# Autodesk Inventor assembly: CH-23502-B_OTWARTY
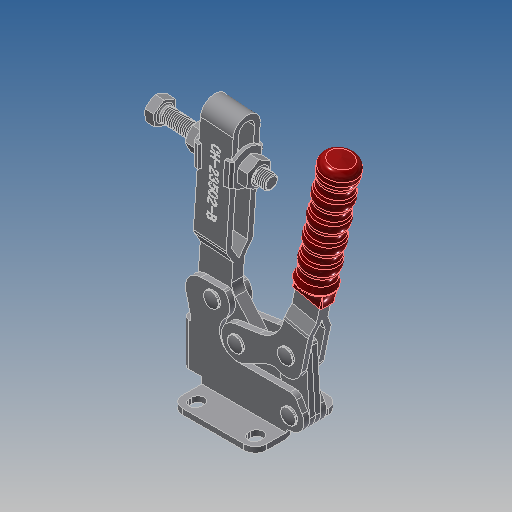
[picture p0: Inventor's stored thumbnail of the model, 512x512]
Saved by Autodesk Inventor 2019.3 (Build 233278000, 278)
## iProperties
Company: ·L?¤¤?
Created: 2010-06
Part Number: CH-23502-B_OTWARTY
Material: Ogólny
Description: STEP AP203
Document SubType Name: Assembly
Designer: CADENGINEERING4
Sending System: SolidWorks 2005179
Preprocessor: SwSTEP 2.0
Title: CH-23502-B.STEP
Author: ·L?¥Î?
Revision Number: ANY
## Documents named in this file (11)
- E:\STRONA\Horizontal toggle clamp\CH-23502-B\CH-23502-B_OTWARTY.iam
- E:\STRONA\Horizontal toggle clamp\CH-23502-B\CH-FC-107512___.ipt
- E:\STRONA\Horizontal toggle clamp\CH-23502-B\23502-B-05___.ipt
- E:\STRONA\Horizontal toggle clamp\CH-23502-B\23502-B-06___.ipt
- E:\STRONA\Horizontal toggle clamp\CH-23502-B\M10___.ipt
- E:\STRONA\Horizontal toggle clamp\CH-23502-B\23502-B-04___.ipt
- E:\STRONA\Horizontal toggle clamp\CH-23502-B\23502-B-07___.ipt
- E:\STRONA\Horizontal toggle clamp\CH-23502-B\23502-B-03___.ipt
- E:\STRONA\Horizontal toggle clamp\CH-23502-B\FW380___.ipt
- E:\STRONA\Horizontal toggle clamp\CH-23502-B\23502-B-02___.ipt
- E:\STRONA\Horizontal toggle clamp\CH-23502-B\23502-B-01___.ipt
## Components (19 placed, 19 different names)
1. CH-FC-107512_??_1 — Zestawiające:5, Zestawiające:7, Równoległe:1, Zestawiające:9, Zestawiające:11, Zestawiające:13
2. 23502-B-05_??_2 — Zestawiające:14, Zestawiające:15
3. 23502-B-06_??_3 — Zestawiające:38, Zestawiające:39
4. M10_??_4 — Zestawiające:11, Zestawiające:12
5. 23502-B-04_??_5 — Zestawiające:22, Zestawiające:23, Zestawiające:24, Zestawiające:25, Zestawiające:26, Zestawiające:34
6. 23502-B-05_??_6 — Zestawiające:16, Zestawiające:17, Zestawiające:18
7. M10_??_7 — Zestawiające:7, Zestawiające:8, Równoległe:1
8. 23502-B-07_??_8 — Zestawiające:1, Zestawiające:2, Zestawiające:3
9. 23502-B-05_??_9 — Zestawiające:29, Zestawiające:32, Zestawiające:34
10. 23502-B-04_??_10 — Zestawiające:22, Zestawiające:23, Zestawiające:24, Zestawiające:33
11. 23502-B-03_??_11 — Zestawiające:1, Zestawiające:2, Zestawiające:3, Zestawiające:29, Zestawiające:30, Zestawiające:31, Zestawiające:32, Zestawiające:33, Zestawiające:35, Zestawiające:36, Zestawiające:38, Zestawiające:39, Przejściowe:1
12. 23502-B-06_??_12 — Zestawiające:27, Zestawiające:28
13. FW380_??_13 — Zestawiające:9, Zestawiające:10, Zestawiające:12
14. FW380_??_14 — Zestawiające:4, Zestawiające:5, Zestawiające:6, Zestawiające:8
15. 23502-B-06_??_15 — Zestawiające:20, Zestawiające:21
16. 23502-B-02_??_16 — Zestawiające:4, Zestawiające:6, Zestawiające:10, Zestawiające:13, Zestawiające:18, Zestawiające:19, Zestawiające:37
17. 23502-B-06_??_17 — Zestawiające:35, Zestawiające:36
18. 23502-B-05_??_18 — Zestawiające:30, Zestawiające:31, Zestawiające:37
19. 23502-B-01_??_19 — Zestawiające:14, Zestawiające:15, Zestawiające:16, Zestawiające:17, Zestawiające:19, Zestawiające:20, Zestawiające:21, Zestawiające:25, Zestawiające:26, Zestawiające:27, Zestawiające:28, Przejściowe:1
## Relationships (41: Mate 39, Flush 1, Transitional 1)
- Zestawiające:1 [Mate]: 23502-B-07_??_8 ↔ 23502-B-03_??_11
- Zestawiające:2 [Mate]: 23502-B-07_??_8 ↔ 23502-B-03_??_11
- Zestawiające:3 [Mate]: 23502-B-07_??_8 ↔ 23502-B-03_??_11
- Zestawiające:4 [Mate]: FW380_??_14 ↔ 23502-B-02_??_16
- Zestawiające:5 [Mate]: CH-FC-107512_??_1 ↔ FW380_??_14
- Zestawiające:6 [Mate]: FW380_??_14 ↔ 23502-B-02_??_16
- Zestawiające:7 [Mate]: CH-FC-107512_??_1 ↔ M10_??_7
- Zestawiające:8 [Mate]: M10_??_7 ↔ FW380_??_14
- Równoległe:1 [Flush]: CH-FC-107512_??_1 ↔ M10_??_7
- Zestawiające:9 [Mate]: CH-FC-107512_??_1 ↔ FW380_??_13
- Zestawiające:10 [Mate]: FW380_??_13 ↔ 23502-B-02_??_16
- Zestawiające:11 [Mate]: CH-FC-107512_??_1 ↔ M10_??_4
- Zestawiające:12 [Mate]: M10_??_4 ↔ FW380_??_13
- Zestawiające:13 [Mate]: CH-FC-107512_??_1 ↔ 23502-B-02_??_16
- Zestawiające:14 [Mate]: 23502-B-05_??_2 ↔ 23502-B-01_??_19
- Zestawiające:15 [Mate]: 23502-B-05_??_2 ↔ 23502-B-01_??_19
- Zestawiające:16 [Mate]: 23502-B-05_??_6 ↔ 23502-B-01_??_19
- Zestawiające:17 [Mate]: 23502-B-05_??_6 ↔ 23502-B-01_??_19
- Zestawiające:18 [Mate]: 23502-B-05_??_6 ↔ 23502-B-02_??_16
- Zestawiające:19 [Mate]: 23502-B-02_??_16 ↔ 23502-B-01_??_19
- Zestawiające:20 [Mate]: 23502-B-06_??_15 ↔ 23502-B-01_??_19
- Zestawiające:21 [Mate]: 23502-B-06_??_15 ↔ 23502-B-01_??_19
- Zestawiające:22 [Mate]: 23502-B-04_??_5 ↔ 23502-B-04_??_10
- Zestawiające:23 [Mate]: 23502-B-04_??_5 ↔ 23502-B-04_??_10
- Zestawiające:24 [Mate]: 23502-B-04_??_5 ↔ 23502-B-04_??_10
- Zestawiające:25 [Mate]: 23502-B-04_??_5 ↔ 23502-B-01_??_19
- Zestawiające:26 [Mate]: 23502-B-04_??_5 ↔ 23502-B-01_??_19
- Zestawiające:27 [Mate]: 23502-B-06_??_12 ↔ 23502-B-01_??_19
- Zestawiające:28 [Mate]: 23502-B-06_??_12 ↔ 23502-B-01_??_19
- Zestawiające:29 [Mate]: 23502-B-05_??_9 ↔ 23502-B-03_??_11
- Zestawiające:30 [Mate]: 23502-B-03_??_11 ↔ 23502-B-05_??_18
- Zestawiające:31 [Mate]: 23502-B-03_??_11 ↔ 23502-B-05_??_18
- Zestawiające:32 [Mate]: 23502-B-05_??_9 ↔ 23502-B-03_??_11
- Zestawiające:33 [Mate]: 23502-B-04_??_10 ↔ 23502-B-03_??_11
- Zestawiające:34 [Mate]: 23502-B-04_??_5 ↔ 23502-B-05_??_9
- Zestawiające:35 [Mate]: 23502-B-03_??_11 ↔ 23502-B-06_??_17
- Zestawiające:36 [Mate]: 23502-B-03_??_11 ↔ 23502-B-06_??_17
- Zestawiające:37 [Mate]: 23502-B-02_??_16 ↔ 23502-B-05_??_18
- Zestawiające:38 [Mate]: 23502-B-06_??_3 ↔ 23502-B-03_??_11
- Zestawiające:39 [Mate]: 23502-B-06_??_3 ↔ 23502-B-03_??_11
- Przejściowe:1 [Transitional]: 23502-B-03_??_11 ↔ 23502-B-01_??_19
